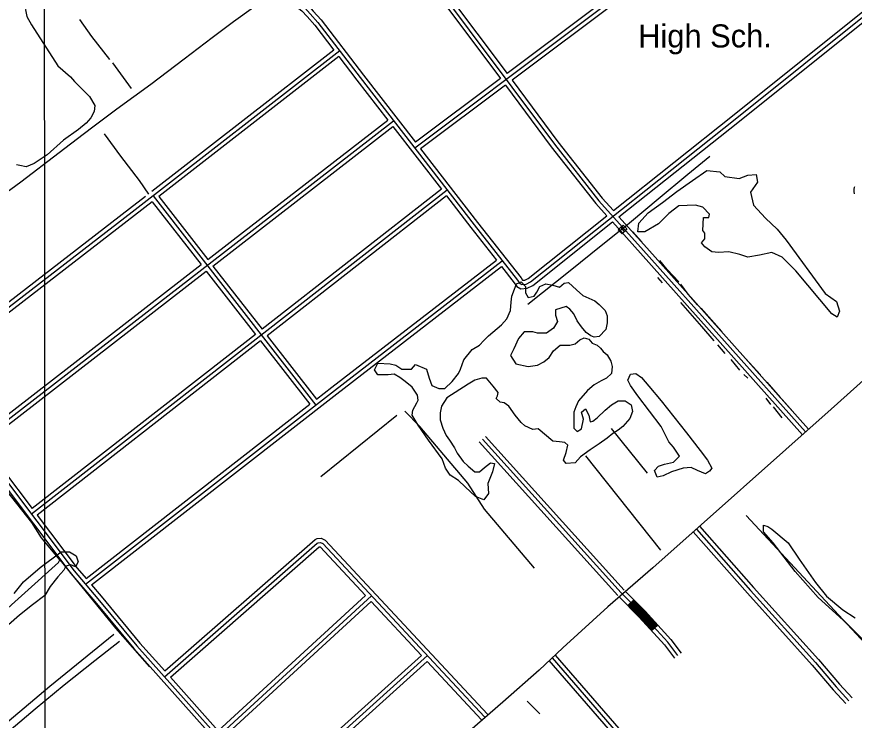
# Model space of a CAD drawing. Extents: x 3297772 to 3335630, y 634068 to 659439.
# Drawn here: x 3307038 to 3310052, y 643022 to 645553 of the extents above; entities that cross this region are included whole.
import ezdxf

# ---------------------------------------------------------------- set-up
doc = ezdxf.new("R2010")
doc.units = 0
for name, color, linetype in [('V-BLDG-IDEN', 7, 'Continuous'), ('V-BRDG-OTLN', 7, 'Continuous'), ('V-DTCH-CNTR', 7, 'Continuous'), ('V-GRID-MAJR', 7, 'Continuous'), ('V-ROAD-CNTR', 7, 'Continuous'), ('V-SITE-VEGE', 7, 'Continuous'), ('V-TOPO-SHOR', 7, 'Continuous')]:
    doc.layers.add(name, color=color, linetype=linetype)

msp = doc.modelspace()

# ---------------------------------------------------------------- linework, layer by layer
at = {"layer": 'V-BRDG-OTLN'}
msp.add_line((3309225.1, 644780.6), (3309211.7, 644795.6), dxfattribs=at)
msp.add_lwpolyline([(3309202.4, 644786.4), (3309211.7, 644795.6), (3309219.7, 644803.5), (3309233.8, 644789.3), (3309225.1, 644780.6), (3309216.5, 644772.2)], close=True, dxfattribs=at)
at = {"layer": 'V-DTCH-CNTR'}
msp.add_lwpolyline([(3306701.5, 642765.8), (3306840.5, 642878.9), (3307157, 643145.1), (3307387.3, 643331.3)], dxfattribs=at)
at = {"layer": 'V-GRID-MAJR'}
msp.add_spline([(3307142.7, 639451.9), (3307140.5, 642480.6), (3307136.1, 648542), (3307131.6, 654603.4), (3307129.4, 657636)], degree=3, dxfattribs=at)
at = {"layer": 'V-ROAD-CNTR'}
for p, q in [((3309258.4, 643455.6), (3309237.1, 643434.5)), ((3309344.7, 643364.3), (3309322.5, 643344.1))]:
    msp.add_line(p, q, dxfattribs=at)
for points in [[(3309326.4, 643570.3), (3309969, 644140.9), (3310396.4, 644525.1), (3310968, 645034.1), (3311417.2, 645433.8), (3312033, 645982.1), (3312324.2, 646235.2), (3312530.8, 646406.6), (3312939.4, 646738.7), (3313345.1, 647067.1), (3313626.7, 647296.1)], [(3310752.4, 646791.8), (3309595.6, 645925.3), (3308470.3, 645080.2)], [(3307115.5, 646688.2), (3307328, 646492.3), (3307398.2, 646420.3), (3307478, 646326.7), (3307583.5, 646187), (3307837.9, 645822.4), (3307879.1, 645766), (3307913.8, 645726.6), (3307954.3, 645686.8), (3308041.9, 645609.3), (3308074.7, 645584.9), (3308094, 645563.2), (3308121.8, 645532.6), (3308274.3, 645333.6), (3308684, 644803.9), (3308840.4, 644604.7), (3308847.8, 644593.6), (3308855.7, 644589.5), (3308870.6, 644590.6), (3308886.4, 644598.9), (3309628.9, 645189.3), (3310352.4, 645769.5)], [(3307366.2, 646431.7), (3307387.1, 646410.2), (3307466.3, 646317.3), (3307571.4, 646178.2), (3307825.7, 645813.6), (3307867.4, 645756.6), (3307902.9, 645716.3), (3307944.1, 645675.8), (3308032.4, 645597.7), (3308064.5, 645573.7), (3308082.9, 645553.1), (3308110.3, 645522.9), (3308179.2, 645433)], [(3310037.5, 646237.5), (3309604.6, 645913.3), (3308820.2, 645324.1)], [(3308359.1, 645916), (3308973.3, 645094.2), (3309133, 644891), (3309293.6, 644711.8), (3309876.2, 644059)], [(3308356.1, 645894.9), (3308778.2, 645330.2)], [(3309419.5, 645811.8), (3308802.2, 645348.2)], [(3309185, 644855.5), (3309619.6, 645201), (3310334, 645773.9)], [(3308025.5, 645643.9), (3308051.4, 645621), (3308084.9, 645596), (3308105.2, 645573.2), (3308133.3, 645542.2), (3308286.1, 645342.7), (3308473.1, 645101)], [(3308584.1, 645639.9), (3308802.2, 645348.2)], [(3309205.1, 644833.1), (3309638.3, 645177.6), (3310251.3, 645669.2)], [(3308200.2, 645430.3), (3307453, 644849.7), (3306698.5, 644267.7)], [(3308179.2, 645433), (3307524.2, 644924)], [(3308197.5, 645409.2), (3307549.4, 644905.6)], [(3308197.5, 645409.2), (3308262.4, 645324.4), (3308373.2, 645181.1)], [(3308778.2, 645330.2), (3308473.1, 645101)], [(3308820.2, 645324.1), (3308985.2, 645103.3), (3309144.5, 644900.7), (3309185, 644855.5)], [(3308796.2, 645306.1), (3308491.5, 645077.3)], [(3308796.2, 645306.1), (3308961.4, 645085), (3309121.5, 644881.4), (3309161.5, 644836.8)], [(3306894.9, 644018), (3307826.2, 644738.6), (3308394.3, 645178.4)], [(3307725.4, 644679.6), (3307817, 644750.5), (3308373.2, 645181.1)], [(3307743.8, 644655.9), (3307835.4, 644726.7), (3308391.6, 645157.4)], [(3308391.6, 645157.4), (3308565.9, 644932)], [(3307352.5, 645131.1), (3307411.5, 645051.6), (3307478.2, 644963.5), (3307512.7, 644915.1)], [(3308491.5, 645077.3), (3308695.9, 644813.1), (3308852.6, 644613.5), (3308858.1, 644605.1), (3308858.8, 644604.8), (3308866.4, 644605.3), (3308878.1, 644611.5), (3309161.5, 644836.8)], [(3306228.5, 644983), (3306438.5, 644641.8), (3306534.4, 644487), (3306623.3, 644363.4), (3306974.7, 643916.6), (3307244.1, 643559.8), (3307330.3, 643458.7), (3307470.2, 643290), (3307953.7, 642747.9)], [(3308586.9, 644929.4), (3307818.3, 644329.8), (3307090.7, 643763)], [(3308565.9, 644932), (3307920.7, 644428.7)], [(3310052.1, 644940.5), (3310051.5, 644938.2), (3310051.1, 644935.9), (3310050.7, 644933.6), (3310050.5, 644931.2), (3310050.3, 644928.9), (3310050.3, 644926.5), (3310050.4, 644924.2), (3310050.7, 644921.8), (3310051, 644919.5), (3310051.4, 644917.2), (3310051.9, 644915.3)], [(3307500.9, 644905.9), (3307443.8, 644861.6), (3306701.1, 644288.7)], [(3307525.7, 644887.2), (3307462.2, 644837.9), (3306719.7, 644265.1)], [(3307525.7, 644887.2), (3307701.7, 644661.2)], [(3307528.4, 644908.3), (3308114, 644156)], [(3307549.4, 644905.6), (3307725.4, 644679.6)], [(3308584.3, 644908.3), (3307939.1, 644405)], [(3308584.3, 644908.3), (3308672.2, 644794.6), (3308764.1, 644677.6)], [(3309205.1, 644833.1), (3309304.8, 644721.8), (3309887.4, 644068.9)], [(3308782.6, 644654), (3308828.2, 644595.9), (3308837.4, 644582.1), (3308852.5, 644574.2), (3308874.9, 644575.9), (3308894.6, 644586.2), (3309181.5, 644814.4)], [(3309181.5, 644814.4), (3309282.4, 644701.8), (3309865, 644049)], [(3306389.2, 644693.2), (3306425.7, 644633.9), (3306522, 644478.6), (3306611.3, 644354.4), (3306962.8, 643907.5), (3307232.4, 643550.4), (3307318.9, 643449.1), (3307458.8, 643280.2), (3307942.5, 642737.9)], [(3308116.6, 644177), (3308171.9, 644220), (3308764.1, 644677.6)], [(3306897.5, 644039), (3307701.7, 644661.2)], [(3307285.3, 643511.5), (3308181.1, 644208.1), (3308785.2, 644675)], [(3307306.9, 643509.3), (3308190.3, 644196.3), (3308782.6, 644654)], [(3307743.8, 644655.9), (3307920.7, 644428.7)], [(3306916.1, 644015.4), (3307720.1, 644637.5)], [(3307720.1, 644637.5), (3307897, 644410.3)], [(3307897, 644410.3), (3307809.1, 644341.6), (3307093.5, 643784.1)], [(3307939.1, 644405), (3308116.6, 644177)], [(3307915.5, 644386.6), (3307827.5, 644318), (3307111.6, 643760.2)], [(3307915.5, 644386.6), (3308092.9, 644158.6)], [(3307287.4, 643532.2), (3308092.9, 644158.6)], [(3308724.7, 644043.2), (3309223.7, 643490.6)], [(3306916.1, 644015.4), (3306986.6, 643925.8), (3307093.5, 643784.1)], [(3308702.4, 644023.1), (3309201.4, 643470.5)], [(3308713.5, 644033.2), (3309212.5, 643480.5)], [(3307111.6, 643760.2), (3307255.8, 643569.2), (3307287.4, 643532.2)], [(3309495, 643719.9), (3309689.6, 643499.4), (3309923.2, 643240.1), (3309998.5, 643151.9), (3310043.7, 643102.6)], [(3309472.5, 643700.1), (3309667.2, 643479.5), (3309900.6, 643220.4), (3309976, 643132), (3310021.7, 643082.3)], [(3309483.7, 643710), (3309678.4, 643489.4), (3309911.9, 643230.2), (3309987.2, 643141.9), (3310032.7, 643092.5)], [(3307569.5, 643178.6), (3308119.2, 643659.5), (3308122.7, 643660.7), (3308131.1, 643661.6), (3308139.1, 643657.8), (3308721.4, 643034.1)], [(3307570.8, 643199.7), (3308111.5, 643672.7), (3308119.4, 643675.4), (3308133.6, 643677), (3308148.1, 643670.2), (3308732.4, 643044.3)], [(3307590.8, 643177.3), (3308126.8, 643646.3), (3308125.9, 643646), (3308128.5, 643646.2), (3308130.1, 643645.5), (3308293, 643471)], [(3309326.4, 643570.3), (3309165.3, 643430.4), (3309003.4, 643283.1), (3308917.5, 643202.5), (3308786.8, 643087.7), (3308640.9, 642960.1), (3308363.3, 642711.9), (3308116.7, 642490)], [(3307306.9, 643509.3), (3307341.8, 643468.4), (3307481.5, 643299.8), (3307570.8, 643199.7)], [(3308314.3, 643470.2), (3307761.8, 642963)], [(3308293, 643471), (3307762.8, 642984.4)], [(3309417, 643254.8), (3309380.7, 643302.5), (3309288.6, 643403.7), (3309212.5, 643480.5)], [(3309228.7, 643485.5), (3309299.5, 643414), (3309392.2, 643312.1), (3309428.9, 643263.9)], [(3308313.5, 643449.1), (3307782.8, 642962)], [(3308313.5, 643449.1), (3308494.2, 643255.4)], [(3309206, 643465.8), (3309277.7, 643393.4), (3309369.1, 643292.9), (3309405, 643245.7)], [(3309243.5, 643440.8), (3309284.2, 643399.6), (3309329.2, 643350.2)], [(3309245.6, 643442.9), (3309286.4, 643401.6), (3309331.4, 643352.2)], [(3309247.7, 643445), (3309288.6, 643403.7), (3309333.6, 643354.2)], [(3309249.8, 643447.1), (3309290.8, 643405.8), (3309335.8, 643356.3)], [(3309252, 643449.2), (3309292.9, 643407.8), (3309338.1, 643358.3)], [(3309254.1, 643451.3), (3309295.1, 643409.9), (3309340.3, 643360.3)], [(3309256.2, 643453.5), (3309297.3, 643412), (3309342.5, 643362.3)], [(3309239.2, 643436.6), (3309279.9, 643395.5), (3309324.7, 643346.2)], [(3309241.3, 643438.7), (3309282.1, 643397.5), (3309327, 643348.2)], [(3308515.6, 643254.5), (3307953.7, 642747.9)], [(3308494.2, 643255.4), (3307954.8, 642769.2)], [(3308514.7, 643233.5), (3307975.1, 642747)], [(3308514.7, 643233.5), (3308710.5, 643023.8)], [(3308953, 643236.6), (3309245.1, 642899.9), (3309501.3, 642614.2), (3309577.6, 642530.3)], [(3308964.4, 643246.4), (3309256.3, 642909.8), (3309512.5, 642624.2), (3309588.7, 642540.4)], [(3308975.7, 643256.3), (3309267.6, 642919.7), (3309523.6, 642634.3), (3309599.8, 642550.5)], [(3307590.8, 643177.3), (3307762.8, 642984.4)]]:
    msp.add_lwpolyline(points, dxfattribs=at)
at = {"layer": 'V-SITE-VEGE'}
for points in [[(3307029.8, 645626.8), (3307049.4, 645636.6), (3307064.2, 645639.1), (3307074, 645639.1), (3307078.9, 645631.7), (3307074, 645597.3), (3307069.1, 645577.6), (3307074, 645553.1), (3307091.2, 645523.6), (3307185.6, 645375.9), (3307231.2, 645336.8), (3307245.9, 645319.6), (3307300, 645265.5), (3307319.6, 645233.5), (3307317.2, 645211.4), (3307304.9, 645189.3), (3307287.7, 645169.6), (3307260.7, 645147.5), (3307206.6, 645108.2), (3307147.7, 645056.6), (3307101, 645024.6), (3307071.5, 645012.3), (3307049.4, 645017.2), (3307037.1, 645019.7)], [(3308686.5, 644245.4), (3308661.9, 644230.7), (3308585.8, 644181.5), (3308566.1, 644152), (3308561.2, 644127.4), (3308561.2, 644102.8), (3308571.1, 644073.3), (3308583.3, 644046.3), (3308595.6, 644029.1), (3308612.8, 644002.1), (3308622.6, 643982.4), (3308644.7, 643952.9), (3308661.9, 643935.7), (3308686.5, 643916), (3308703.7, 643916), (3308720.9, 643930.8), (3308743, 643948), (3308757.7, 643945.5), (3308750.4, 643916), (3308733.2, 643874.2), (3308735.6, 643837.4), (3308718.4, 643815.3), (3308689, 643827.5), (3308652.1, 643862), (3308627.6, 643884.1), (3308598.1, 643903.7), (3308580.9, 643928.3), (3308568.6, 643962.7), (3308519.5, 644029.1), (3308482.6, 644083.2), (3308460.5, 644120), (3308463, 644137.3), (3308477.7, 644164.3), (3308482.6, 644174.1), (3308480.2, 644191.3), (3308460.5, 644220.8), (3308436, 644240.5), (3308416.3, 644255.2), (3308396.7, 644267.5), (3308374.6, 644265.1), (3308337.7, 644265.1), (3308325.4, 644282.3), (3308337.7, 644306.9), (3308381.9, 644304.4), (3308401.6, 644299.5), (3308423.7, 644284.7), (3308458.1, 644284.7), (3308472.8, 644301.9), (3308512.1, 644284.7), (3308521.9, 644252.8), (3308531.8, 644225.7), (3308556.3, 644215.9), (3308578.4, 644215.9), (3308605.4, 644240.5), (3308627.6, 644270), (3308634.9, 644284.7), (3308647.2, 644319.1), (3308676.7, 644356), (3308703.7, 644370.8), (3308718.4, 644388), (3308735.6, 644405.2), (3308782.3, 644444.5), (3308801.9, 644466.6), (3308814.2, 644496.1), (3308816.7, 644525.6), (3308819.1, 644547.7), (3308829, 644572.3), (3308836.3, 644592), (3308853.5, 644599.4), (3308868.3, 644582.1), (3308868.3, 644560), (3308878.1, 644542.8), (3308900.2, 644547.7), (3308910, 644562.5), (3308919.8, 644582.1), (3308942, 644592), (3308966.5, 644587.1), (3308991.1, 644579.7), (3309008.3, 644594.4), (3309023, 644596.9), (3309052.5, 644569.9), (3309074.6, 644550.2)], [(3309074.6, 644550.2), (3309118.8, 644530.5), (3309133.5, 644518.2), (3309155.6, 644496.1), (3309163, 644476.5), (3309163, 644451.9), (3309158.1, 644427.3), (3309133.5, 644402.7), (3309116.3, 644400.3), (3309104.1, 644405.2), (3309086.9, 644417.5), (3309069.7, 644437.1), (3309054.9, 644459.3), (3309042.7, 644483.8), (3309027.9, 644501), (3309015.6, 644510.9), (3308976.3, 644498.6), (3308976.3, 644478.9), (3308983.7, 644456.8), (3308969, 644432.2), (3308944.4, 644415), (3308912.5, 644415), (3308895.3, 644419.9), (3308863.4, 644419.9), (3308843.7, 644395.3), (3308826.5, 644358.5), (3308814.2, 644333.9), (3308833.9, 644304.4), (3308878.1, 644294.6), (3308912.5, 644299.5), (3308934.6, 644311.8), (3308954.2, 644326.5), (3308969, 644351.1), (3308993.5, 644370.8), (3309027.9, 644370.8), (3309047.6, 644375.7), (3309064.8, 644390.4), (3309079.5, 644397.8), (3309096.7, 644392.9), (3309109, 644378.1), (3309126.2, 644370.8), (3309138.4, 644360.9), (3309148.3, 644348.6), (3309163, 644336.4), (3309175.3, 644314.2), (3309180.2, 644294.6), (3309177.8, 644270), (3309160.6, 644252.8), (3309140.9, 644242.9), (3309116.3, 644228.2), (3309091.8, 644208.5), (3309059.9, 644171.7), (3309050, 644149.5), (3309042.7, 644129.9), (3309042.7, 644073.3), (3309054.9, 644061.1), (3309069.7, 644070.9), (3309077, 644105.3), (3309069.7, 644129.9), (3309084.4, 644142.2), (3309096.7, 644120), (3309101.6, 644095.5), (3309111.4, 644097.9), (3309126.2, 644110.2), (3309155.6, 644137.3), (3309177.8, 644156.9), (3309202.3, 644171.7), (3309226.9, 644171.7), (3309249, 644156.9), (3309253.9, 644132.3), (3309244.1, 644107.8), (3309219.5, 644078.3), (3309202.3, 644066), (3309182.7, 644053.7), (3309163, 644036.5), (3309133.5, 644016.8), (3309101.6, 643994.7), (3309067.2, 643970.1), (3309047.6, 643948), (3309015.6, 643945.5), (3309005.8, 643957.8), (3309015.6, 643984.9), (3309020.6, 644011.9), (3309010.7, 644021.7), (3308991.1, 644024.2), (3308966.5, 644026.6), (3308914.9, 644070.9), (3308895.3, 644068.4), (3308865.8, 644080.7), (3308853.5, 644093), (3308831.4, 644120), (3308809.3, 644152), (3308792.1, 644164.3), (3308777.4, 644166.7), (3308762.6, 644179), (3308767.6, 644188.9), (3308770, 644201.2), (3308752.8, 644223.3), (3308728.3, 644252.8), (3308711.1, 644252.8), (3308686.5, 644245.4)], [(3310118.5, 643277), (3310025.2, 643370.4), (3309922, 643463.8), (3309838.5, 643557.2), (3309759.9, 643660.4), (3309725.5, 643699.7), (3309725.5, 643724.3), (3309740.2, 643719.4), (3309755, 643709.6), (3309813.9, 643660.4), (3309853.2, 643601.4), (3309912.2, 643517.8), (3309951.5, 643468.7), (3310010.4, 643419.5), (3310054.6, 643390)], [(3307028.5, 643478.5), (3307062.9, 643520.3), (3307121.9, 643571.9), (3307198, 643628.4), (3307227.5, 643628.4), (3307252.1, 643613.7), (3307259.4, 643591.6), (3307249.6, 643574.4), (3307232.4, 643581.7), (3307215.2, 643576.8), (3307207.8, 643562.1), (3307185.7, 643537.5), (3307158.7, 643503.1), (3307139.1, 643471.1), (3307094.9, 643436.7), (3307048.2, 643399.9), (3307008.9, 643365.4)]]:
    msp.add_lwpolyline(points, dxfattribs=at)
for points in [[(3309732.9, 644828), (3309774.6, 644788.6), (3309806.5, 644749.3), (3309946.6, 644557.6), (3309988.3, 644528.1), (3309998.1, 644493.7), (3309990.8, 644471.5), (3309971.1, 644483.8), (3309840.9, 644638.7), (3309791.8, 644687.8), (3309755, 644705.1), (3309710.8, 644695.2), (3309669, 644687.8), (3309639.5, 644697.7), (3309600.2, 644707.5), (3309563.4, 644705.1), (3309538.8, 644707.5), (3309514.3, 644724.7), (3309502, 644739.5), (3309514.3, 644754.2), (3309514.3, 644773.9), (3309506.9, 644783.7), (3309509.3, 644830.4), (3309529, 644830.4), (3309531.4, 644842.7), (3309506.9, 644867.3), (3309479.9, 644874.7), (3309420.9, 644872.2), (3309384.1, 644845.2), (3309347.2, 644808.3), (3309298.1, 644778.8), (3309273.5, 644778.8), (3309276, 644810.7), (3309310.4, 644847.6), (3309362, 644884.5), (3309413.6, 644923.8), (3309470, 644963.1), (3309521.6, 645000), (3309568.3, 644995.1), (3309585.5, 644977.9), (3309637.1, 644970.5), (3309669, 644982.8), (3309698.5, 644985.3), (3309703.4, 644958.2), (3309678.8, 644921.4), (3309688.6, 644874.7)], [(3309357.1, 644078.3), (3309273.5, 644188.9), (3309246.5, 644225.7), (3309236.7, 644245.4), (3309246.5, 644267.5), (3309266.2, 644270), (3309285.8, 644255.2), (3309312.8, 644223.3), (3309357.1, 644171.7), (3309447.9, 644056.1), (3309497.1, 643992.2), (3309524.1, 643957.8), (3309538.8, 643928.3), (3309531.4, 643918.5), (3309516.7, 643908.7), (3309487.2, 643920.9), (3309465.1, 643930.8), (3309435.7, 643928.3), (3309393.9, 643916), (3309364.4, 643901.3), (3309342.3, 643896.4), (3309332.5, 643920.9), (3309347.2, 643935.7), (3309369.3, 643943.1), (3309401.3, 643950.4), (3309423.4, 643972.6), (3309401.3, 644004.5), (3309384.1, 644024.2)]]:
    msp.add_lwpolyline(points, close=True, dxfattribs=at)
at = {"layer": 'V-TOPO-SHOR'}
for p, q in [((3307382.1, 645386.4), (3307450.2, 645294.1)), ((3309287.2, 644742.7), (3309254.5, 644779)), ((3309361.6, 644595.7), (3309344.5, 644614.6)), ((3309587.6, 644341.8), (3309560.6, 644372.4)), ((3309639.8, 644281.4), (3309608.3, 644319.5)), ((3309714.2, 644264.3), (3309660.8, 644322.8)), ((3309669, 644252.2), (3309654.7, 644266.2)), ((3309786.8, 644182.8), (3309738.1, 644237.7)), ((3309751.7, 644157.6), (3309734.3, 644180.7)), ((3309831.2, 644132.3), (3309792.8, 644176.1)), ((3309792.3, 644109.6), (3309760.7, 644149.1)), ((3308132.3, 643898.9), (3308406.3, 644120)), ((3309307.4, 643910.9), (3309177.7, 644071.9)), ((3309355.5, 643634.5), (3309086.4, 643973.4)), ((3310289.3, 643083.6), (3309662.8, 643758.6)), ((3308874.9, 643090.2), (3308920.5, 643044.6))]:
    msp.add_line(p, q, dxfattribs=at)
for points in [[(3307960.1, 645636), (3307889.4, 645585.5), (3307817.5, 645534.3), (3307741.1, 645477), (3307640.2, 645399.6), (3307520.9, 645309.3), (3307398.1, 645219.8), (3307316.5, 645159), (3307277, 645129.4), (3307191, 645063.4), (3307053.2, 644957.4), (3306899.7, 644846.2), (3306839.2, 644803.7), (3306807.6, 644778.4), (3306713.7, 644707.2), (3306616.3, 644633.3), (3306515.6, 644560.5)], [(3307264.1, 645543), (3307307.5, 645481.6), (3307372.2, 645398.5)], [(3309531.8, 645049.6), (3309453.4, 644985.3), (3309346.1, 644896.9), (3309249.8, 644816.4), (3309226.9, 644797.4)], [(3309226.9, 644797.4), (3309206.1, 644780.2), (3309141.6, 644729.2), (3309029.5, 644638.3), (3308877.4, 644517.4)], [(3309420.3, 644598.9), (3309378.5, 644643.2), (3309351.9, 644675.5)], [(3309488, 644517), (3309454, 644554.4), (3309427.6, 644591.2)], [(3307193.3, 643598.9), (3307126.6, 643678.3), (3307092.1, 643733.5), (3306880.4, 644000.3), (3306484.8, 644536.3)], [(3309547.3, 644387.2), (3309502.7, 644438.7), (3309427.1, 644524.4)], [(3309574.8, 644420.9), (3309537.7, 644462.3), (3309500.7, 644504.2)], [(3308901.3, 643569.7), (3308721.1, 643781.1), (3308661, 643874.9), (3308488, 644079.1), (3308435.1, 644134.4)], [(3306602.1, 643076.7), (3306956.3, 643382.7), (3307188.7, 643589.7), (3307193.3, 643598.9), (3307393.4, 643352.8), (3307515.3, 643214.7)], [(3307407.6, 643305.2), (3307318.5, 643235.4), (3307208.7, 643147.9), (3307104.5, 643062.4), (3306915, 642902.7), (3306701, 642731.6)]]:
    msp.add_lwpolyline(points, dxfattribs=at)

# ---------------------------------------------------------------- texts
at = {"layer": 'V-BLDG-IDEN'}
msp.add_text('High Sch.', height=83, rotation=0.0734, dxfattribs=at).set_placement((3309274.1, 645441.8))

doc.saveas('drawing.dxf')
